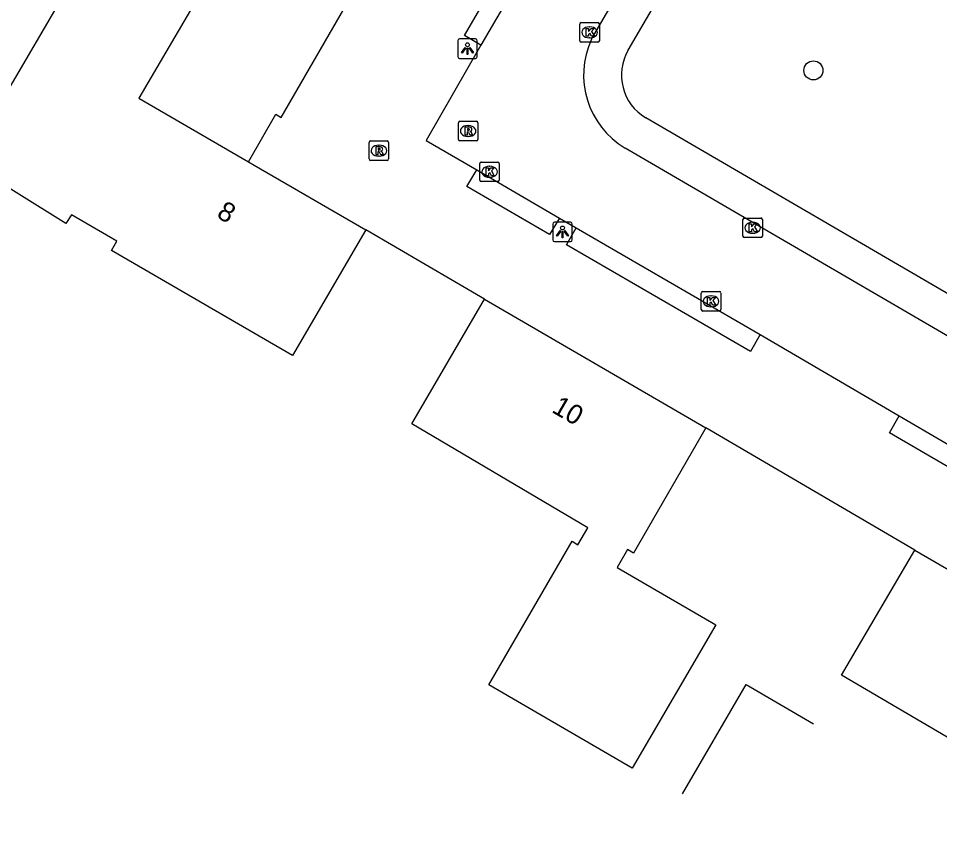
# Model space of a CAD drawing. Extents: x 156502 to 159074, y 384229 to 386094.
# Drawn here: x 157088.76 to 157135.98, y 385827.46 to 385868.93 of the extents above; entities that cross this region are included whole.
import ezdxf

# ---------------------------------------------------------------- set-up
doc = ezdxf.new("R2010")
doc.units = 0
for name, color, linetype in [('IMGEO_Boom', 7, 'Continuous'), ('IMGEO_Hek', 7, 'Continuous'), ('IMGEO_Kolk', 7, 'Continuous'), ('IMGEO_Lichtpunt', 7, 'Continuous'), ('IMGEO_Muur', 7, 'Continuous'), ('IMGEO_Pand', 7, 'Continuous'), ('IMGEO_Pand_nummerreeks', 7, 'Continuous'), ('IMGEO_Parkeervlak_open', 7, 'Continuous'), ('IMGEO_Rijbaan_lokaal_open', 7, 'Continuous'), ('IMGEO_Rioolput', 7, 'Continuous'), ('IMGEO_Voetpad_open', 7, 'Continuous')]:
    doc.layers.add(name, color=color, linetype=linetype)

msp = doc.modelspace()

# ---------------------------------------------------------------- linework, layer by layer
at = {"layer": 'IMGEO_Boom'}
msp.add_circle((157129.509, 385866.262), 0.489, dxfattribs=at)
at = {"layer": 'IMGEO_Hek'}
for points in [[(157101.95, 385864.014), (157102.227, 385863.854), (157105.698, 385869.85)], [(157112.648, 385854.542), (157106.562, 385858.084)], [(157134.715, 385841.68), (157123.992, 385847.954)]]:
    msp.add_lwpolyline(points, dxfattribs=at)
at = {"layer": 'IMGEO_Kolk'}
for p, q in [((157117.536, 385867.785), (157117.536, 385868.637)), ((157117.611, 385868.711), (157118.463, 385868.711)), ((157118.537, 385868.637), (157118.537, 385867.785)), ((157118.024, 385868.491), (157118.049, 385868.491)), ((157118.463, 385867.711), (157117.611, 385867.711)), ((157118.047, 385867.931), (157118.022, 385867.931)), ((157112.407, 385860.641), (157112.407, 385861.493)), ((157112.482, 385861.567), (157113.334, 385861.567)), ((157113.408, 385861.493), (157113.408, 385860.641)), ((157112.895, 385861.347), (157112.92, 385861.347)), ((157113.334, 385860.567), (157112.482, 385860.567)), ((157112.918, 385860.787), (157112.893, 385860.787)), ((157125.969, 385858.698), (157126.821, 385858.698)), ((157125.894, 385857.772), (157125.894, 385858.624)), ((157126.382, 385858.478), (157126.407, 385858.478)), ((157126.895, 385858.624), (157126.895, 385857.772)), ((157126.405, 385857.918), (157126.38, 385857.918)), ((157126.821, 385857.698), (157125.969, 385857.698)), ((157123.838, 385854.929), (157124.69, 385854.929)), ((157123.763, 385854.003), (157123.763, 385854.855)), ((157124.251, 385854.709), (157124.276, 385854.709)), ((157124.764, 385854.855), (157124.764, 385854.003)), ((157124.69, 385853.929), (157123.838, 385853.929)), ((157124.274, 385854.149), (157124.249, 385854.149))]:
    msp.add_line(p, q, dxfattribs=at)
for points in [[(157117.536, 385867.785), (157117.536, 385868.637)], [(157117.611, 385868.711), (157118.463, 385868.711)], [(157118.537, 385868.637), (157118.537, 385867.785)], [(157117.857, 385868.411), (157117.98, 385868.411), (157117.98, 385868.26), (157118.11, 385868.411), (157118.274, 385868.411), (157118.128, 385868.26), (157118.281, 385868.011), (157118.129, 385868.011), (157118.044, 385868.175), (157117.98, 385868.108), (157117.98, 385868.011), (157117.857, 385868.011), (157117.857, 385868.411)], [(157118.463, 385867.711), (157117.611, 385867.711)], [(157112.407, 385860.641), (157112.407, 385861.493)], [(157112.482, 385861.567), (157113.334, 385861.567)], [(157113.408, 385861.493), (157113.408, 385860.641)], [(157112.728, 385861.267), (157112.851, 385861.267), (157112.851, 385861.116), (157112.981, 385861.267), (157113.145, 385861.267), (157112.999, 385861.116), (157113.152, 385860.867), (157113, 385860.867), (157112.915, 385861.031), (157112.851, 385860.964), (157112.851, 385860.867), (157112.728, 385860.867), (157112.728, 385861.267)], [(157113.334, 385860.567), (157112.482, 385860.567)], [(157125.969, 385858.698), (157126.821, 385858.698)], [(157125.894, 385857.772), (157125.894, 385858.624)], [(157126.215, 385858.398), (157126.338, 385858.398), (157126.338, 385858.247), (157126.468, 385858.398), (157126.632, 385858.398), (157126.486, 385858.247), (157126.639, 385857.998), (157126.487, 385857.998), (157126.402, 385858.162), (157126.338, 385858.095), (157126.338, 385857.998), (157126.215, 385857.998), (157126.215, 385858.398)], [(157126.895, 385858.624), (157126.895, 385857.772)], [(157126.821, 385857.698), (157125.969, 385857.698)], [(157123.838, 385854.929), (157124.69, 385854.929)], [(157123.763, 385854.003), (157123.763, 385854.855)], [(157124.084, 385854.629), (157124.207, 385854.629), (157124.207, 385854.478), (157124.337, 385854.629), (157124.501, 385854.629), (157124.355, 385854.478), (157124.508, 385854.229), (157124.356, 385854.229), (157124.271, 385854.393), (157124.207, 385854.326), (157124.207, 385854.229), (157124.084, 385854.229), (157124.084, 385854.629)], [(157124.764, 385854.855), (157124.764, 385854.003)], [(157124.69, 385853.929), (157123.838, 385853.929)]]:
    msp.add_lwpolyline(points, dxfattribs=at)
for centre, start, end in [((157117.613, 385868.635), 91.552, 178.448), ((157117.613, 385868.635), 91.552, 178.448), ((157118.461, 385868.635), 1.552, 88.448), ((157118.461, 385868.635), 1.552, 88.448), ((157117.613, 385867.787), 181.552, 268.448), ((157117.613, 385867.787), 181.552, 268.448), ((157118.461, 385867.787), 271.552, 358.448), ((157118.461, 385867.787), 271.552, 358.448), ((157112.484, 385861.491), 91.552, 178.448), ((157112.484, 385861.491), 91.552, 178.448), ((157113.332, 385861.491), 1.552, 88.448), ((157113.332, 385861.491), 1.552, 88.448), ((157112.484, 385860.643), 181.552, 268.448), ((157112.484, 385860.643), 181.552, 268.448), ((157113.332, 385860.643), 271.552, 358.448), ((157113.332, 385860.643), 271.552, 358.448), ((157125.971, 385858.622), 91.552, 178.448), ((157125.971, 385858.622), 91.552, 178.448), ((157126.819, 385858.622), 1.552, 88.448), ((157126.819, 385858.622), 1.552, 88.448), ((157125.971, 385857.774), 181.552, 268.448), ((157125.971, 385857.774), 181.552, 268.448), ((157126.819, 385857.774), 271.552, 358.448), ((157126.819, 385857.774), 271.552, 358.448), ((157123.84, 385854.853), 91.552, 178.448), ((157123.84, 385854.853), 91.552, 178.448), ((157124.688, 385854.853), 1.552, 88.448), ((157124.688, 385854.853), 1.552, 88.448), ((157123.84, 385854.005), 181.552, 268.448), ((157123.84, 385854.005), 181.552, 268.448), ((157124.688, 385854.005), 271.552, 358.448), ((157124.688, 385854.005), 271.552, 358.448)]:
    msp.add_arc(centre, 0.0765, start, end, dxfattribs=at)
for centre, major_axis, ratio, start_param, end_param in [((157118.023, 385868.211), (-0.387, 0.002), 0.722429, 4.712389, 7.853982), ((157118.048, 385868.211), (-0.39, 0.002), 0.717154, 1.570796, 4.712389), ((157112.894, 385861.067), (-0.387, 0.002), 0.722429, 4.712389, 7.853982), ((157112.919, 385861.067), (-0.39, 0.002), 0.717154, 1.570796, 4.712389), ((157126.381, 385858.198), (-0.387, 0.002), 0.722429, 4.712389, 7.853982), ((157126.406, 385858.198), (-0.39, 0.002), 0.717154, 1.570796, 4.712389), ((157124.25, 385854.429), (-0.387, 0.002), 0.722429, 4.712389, 7.853982), ((157124.275, 385854.429), (-0.39, 0.002), 0.717154, 1.570796, 4.712389)]:
    msp.add_ellipse(centre, major_axis=major_axis, ratio=ratio, start_param=start_param, end_param=end_param, dxfattribs=at)
at = {"layer": 'IMGEO_Lichtpunt'}
for p, q in [((157111.279, 385867.778), (157111.279, 385866.971)), ((157111.279, 385867.778), (157111.279, 385866.971)), ((157112.181, 385867.873), (157111.373, 385867.873)), ((157112.181, 385867.873), (157111.373, 385867.873)), ((157112.275, 385866.971), (157112.275, 385867.778)), ((157112.275, 385866.971), (157112.275, 385867.778)), ((157111.373, 385866.877), (157112.181, 385866.877)), ((157111.373, 385866.877), (157112.181, 385866.877)), ((157116.149, 385858.388), (157116.149, 385857.581)), ((157116.149, 385858.388), (157116.149, 385857.581)), ((157117.051, 385858.483), (157116.243, 385858.483)), ((157117.051, 385858.483), (157116.243, 385858.483)), ((157117.145, 385857.581), (157117.145, 385858.388)), ((157117.145, 385857.581), (157117.145, 385858.388)), ((157116.243, 385857.487), (157117.051, 385857.487)), ((157116.243, 385857.487), (157117.051, 385857.487))]:
    msp.add_line(p, q, dxfattribs=at)
for points in [[(157111.653, 385867.442), (157111.692, 385867.414), (157111.504, 385867.152), (157111.466, 385867.179), (157111.653, 385867.442)], [(157111.755, 385867.394), (157111.802, 385867.394), (157111.802, 385867.072), (157111.755, 385867.072), (157111.755, 385867.394)], [(157111.865, 385867.414), (157111.903, 385867.441), (157112.09, 385867.179), (157112.051, 385867.151), (157111.865, 385867.414)], [(157116.523, 385858.052), (157116.562, 385858.024), (157116.374, 385857.762), (157116.336, 385857.789), (157116.523, 385858.052)], [(157116.625, 385858.004), (157116.672, 385858.004), (157116.672, 385857.682), (157116.625, 385857.682), (157116.625, 385858.004)], [(157116.735, 385858.024), (157116.773, 385858.051), (157116.96, 385857.789), (157116.921, 385857.761), (157116.735, 385858.024)]]:
    msp.add_lwpolyline(points, dxfattribs=at)
for centre in [(157111.778, 385867.576), (157116.648, 385858.186)]:
    msp.add_circle(centre, 0.0994, dxfattribs=at)
for centre, start, end in [((157111.373, 385867.778), 90, 180), ((157111.373, 385867.778), 90, 180), ((157112.181, 385867.778), 0, 90), ((157112.181, 385867.778), 0, 90), ((157111.373, 385866.971), 180, 270), ((157111.373, 385866.971), 180, 270), ((157112.181, 385866.971), 270, 0), ((157112.181, 385866.971), 270, 360), ((157116.243, 385858.388), 90, 180), ((157116.243, 385858.388), 90, 180), ((157117.051, 385858.388), 0, 90), ((157117.051, 385858.388), 0, 90), ((157116.243, 385857.581), 180, 270), ((157116.243, 385857.581), 180, 270), ((157117.051, 385857.581), 270, 0), ((157117.051, 385857.581), 270, 360)]:
    msp.add_arc(centre, 0.0946, start, end, dxfattribs=at)
at = {"layer": 'IMGEO_Muur'}
msp.add_lwpolyline([(157122.793, 385829.183), (157126.065, 385834.799), (157129.521, 385832.785)], dxfattribs=at)
at = {"layer": 'IMGEO_Pand'}
for points in [[(157106.562, 385858.084), (157102.808, 385851.646), (157093.53, 385857.04), (157093.801, 385857.507), (157091.477, 385858.867), (157091.192, 385858.41), (157086.085, 385861.587), (157093.153, 385873.673), (157098.324, 385870.649), (157094.927, 385864.842), (157100.545, 385861.579)], [(157100.545, 385861.579), (157100.836, 385861.41), (157106.562, 385858.084)], [(157123.992, 385847.954), (157120.284, 385841.529), (157119.981, 385841.704), (157119.443, 385840.792), (157124.514, 385837.857), (157120.221, 385830.506), (157112.866, 385834.77), (157117.135, 385842.132), (157117.437, 385841.957), (157117.939, 385842.822), (157108.916, 385848.145), (157112.648, 385854.542)], [(157112.648, 385854.542), (157123.992, 385847.954)], [(157146.045, 385835.121), (157142.29, 385828.637), (157141.989, 385828.812), (157141.44, 385827.871), (157146.528, 385824.906), (157141.519, 385816.264), (157134.144, 385820.573), (157139.17, 385829.213), (157139.464, 385829.042), (157140.002, 385829.967), (157130.951, 385835.263), (157134.715, 385841.68)], [(157134.715, 385841.68), (157146.045, 385835.121)]]:
    msp.add_lwpolyline(points, dxfattribs=at)
at = {"layer": 'IMGEO_Parkeervlak_open'}
for points in [[(157120.018, 385867.301), (157135.456, 385893.714)], [(157175.135, 385832.241), (157120.919, 385863.835)]]:
    msp.add_lwpolyline(points, dxfattribs=at)
msp.add_arc((157122.202, 385866.019), 2.533, 149.5838, 239.5596, dxfattribs=at)
at = {"layer": 'IMGEO_Rijbaan_lokaal_open'}
for points in [[(157118.137, 385867.857), (157133.752, 385894.602)], [(157117.795, 385876.679), (157112.461, 385867.56)], [(157112.461, 385867.56), (157109.666, 385862.678), (157112.261, 385861.167)], [(157174.491, 385830.448), (157119.853, 385862.285)], [(157112.261, 385861.167), (157116.486, 385858.694)], [(157116.486, 385858.694), (157117.345, 385858.202)], [(157117.345, 385858.202), (157126.778, 385852.73)], [(157126.778, 385852.73), (157133.897, 385848.562)], [(157133.897, 385848.562), (157138.584, 385845.831)]]:
    msp.add_lwpolyline(points, dxfattribs=at)
msp.add_arc((157122.079, 385866.021), 4.349, 155.0271, 239.2073, dxfattribs=at)
at = {"layer": 'IMGEO_Rioolput'}
for p, q in [((157111.31, 385862.728), (157111.31, 385863.58)), ((157111.385, 385863.654), (157112.237, 385863.654)), ((157111.798, 385863.434), (157111.823, 385863.434)), ((157112.311, 385863.58), (157112.311, 385862.728)), ((157106.734, 385861.722), (157106.734, 385862.574)), ((157106.809, 385862.648), (157107.661, 385862.648)), ((157107.222, 385862.428), (157107.247, 385862.428)), ((157107.735, 385862.574), (157107.735, 385861.722)), ((157112.237, 385862.654), (157111.385, 385862.654)), ((157111.821, 385862.874), (157111.796, 385862.874)), ((157107.661, 385861.648), (157106.809, 385861.648)), ((157107.245, 385861.868), (157107.22, 385861.868))]:
    msp.add_line(p, q, dxfattribs=at)
for points in [[(157111.31, 385862.728), (157111.31, 385863.58)], [(157111.385, 385863.654), (157112.237, 385863.654)], [(157112.311, 385863.58), (157112.311, 385862.728)], [(157111.899, 385863.352), (157111.647, 385863.354), (157111.647, 385862.954)], [(157111.647, 385862.954), (157111.771, 385862.954), (157111.771, 385863.116), (157111.782, 385863.116)], [(157111.825, 385863.273), (157111.771, 385863.273), (157111.771, 385863.192)], [(157111.771, 385863.192), (157111.823, 385863.192)], [(157111.829, 385863.087), (157111.9, 385862.954), (157112.04, 385862.954), (157111.975, 385863.08)], [(157106.734, 385861.722), (157106.734, 385862.574)], [(157106.809, 385862.648), (157107.661, 385862.648)], [(157107.735, 385862.574), (157107.735, 385861.722)], [(157112.237, 385862.654), (157111.385, 385862.654)], [(157107.323, 385862.346), (157107.071, 385862.348), (157107.071, 385861.948)], [(157107.071, 385861.948), (157107.195, 385861.948), (157107.195, 385862.11), (157107.206, 385862.11)], [(157107.249, 385862.267), (157107.195, 385862.267), (157107.195, 385862.186)], [(157107.195, 385862.186), (157107.247, 385862.186)], [(157107.253, 385862.081), (157107.324, 385861.948), (157107.464, 385861.948), (157107.399, 385862.074)], [(157107.661, 385861.648), (157106.809, 385861.648)]]:
    msp.add_lwpolyline(points, dxfattribs=at)
for centre, radius, start, end in [((157111.387, 385863.578), 0.0765, 91.552, 178.448), ((157111.387, 385863.578), 0.0765, 91.552, 178.448), ((157112.235, 385863.578), 0.0765, 1.552, 88.448), ((157112.235, 385863.578), 0.0765, 1.552, 88.448), ((157111.781, 385863.063), 0.0533, 26.0293, 88.6989), ((157111.807, 385863.381), 0.19, 274.7715, 282.9687), ((157111.831, 385863.177), 0.0964, 77.0061, 93.1865), ((157111.845, 385863.234), 0.0378, 276.6634, 79.6772), ((157111.898, 385863.242), 0.109, 350.3612, 89.416), ((157111.896, 385863.242), 0.112, 277.5842, 350.9817), ((157111.88, 385863.027), 0.108, 29.5134, 73.7905), ((157106.811, 385862.572), 0.0765, 91.552, 178.448), ((157106.811, 385862.572), 0.0765, 91.552, 178.448), ((157107.659, 385862.572), 0.0765, 1.552, 88.448), ((157107.659, 385862.572), 0.0765, 1.552, 88.448), ((157111.387, 385862.73), 0.0765, 181.552, 268.448), ((157111.387, 385862.73), 0.0765, 181.552, 268.448), ((157112.235, 385862.73), 0.0765, 271.552, 358.448), ((157112.235, 385862.73), 0.0765, 271.552, 358.448), ((157107.205, 385862.057), 0.0533, 26.0293, 88.6989), ((157107.231, 385862.375), 0.19, 274.7715, 282.9687), ((157107.255, 385862.171), 0.0964, 77.0061, 93.1865), ((157107.269, 385862.228), 0.0378, 276.6634, 79.6772), ((157107.322, 385862.236), 0.109, 350.3612, 89.416), ((157107.32, 385862.236), 0.112, 277.5842, 350.9817), ((157107.304, 385862.021), 0.108, 29.5134, 73.7905), ((157106.811, 385861.724), 0.0765, 181.552, 268.448), ((157106.811, 385861.724), 0.0765, 181.552, 268.448), ((157107.659, 385861.724), 0.0765, 271.552, 358.448), ((157107.659, 385861.724), 0.0765, 271.552, 358.448)]:
    msp.add_arc(centre, radius, start, end, dxfattribs=at)
for centre, major_axis, ratio, start_param, end_param in [((157111.797, 385863.154), (-0.387, 0.002), 0.722429, 4.712389, 7.853982), ((157111.822, 385863.154), (-0.39, 0.002), 0.717154, 1.570796, 4.712389), ((157107.221, 385862.148), (-0.387, 0.002), 0.722429, 4.712389, 7.853982), ((157107.246, 385862.148), (-0.39, 0.002), 0.717154, 1.570796, 4.712389)]:
    msp.add_ellipse(centre, major_axis=major_axis, ratio=ratio, start_param=start_param, end_param=end_param, dxfattribs=at)
at = {"layer": 'IMGEO_Voetpad_open'}
for points in [[(157112.461, 385867.56), (157111.628, 385868.045), (157116.943, 385877.186), (157117.795, 385876.679)], [(157100.545, 385861.579), (157101.95, 385864.014), (157102.227, 385863.854), (157105.698, 385869.85), (157105.837, 385870.09)], [(157116.486, 385858.694), (157115.987, 385857.851), (157111.749, 385860.312), (157112.261, 385861.167)], [(157126.778, 385852.73), (157126.279, 385851.85), (157116.851, 385857.331), (157117.345, 385858.202)], [(157112.648, 385854.542), (157106.562, 385858.084)], [(157138.584, 385845.831), (157138.076, 385844.975), (157133.418, 385847.696), (157133.897, 385848.562)], [(157134.715, 385841.68), (157123.992, 385847.954)]]:
    msp.add_lwpolyline(points, dxfattribs=at)

# ---------------------------------------------------------------- texts
at = {"layer": 'IMGEO_Pand_nummerreeks'}
for s, rotation, p in [('8', 329.8502, (157098.865, 385858.762)), ('10', 329.8534, (157116.045, 385848.776))]:
    msp.add_text(s, height=1, rotation=rotation, dxfattribs=at).set_placement(p)

doc.saveas('drawing.dxf')
